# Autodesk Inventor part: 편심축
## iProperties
Company: 한국ATC센터
Created: 2014-01
Part Number: 편심축
Document SubType Name: Modeling
Designer: KYOUNG IL JANG
Density: 1 g/cm^3
Material: 기본값
Mass: 122.723 g
Surface Area: 190.471 cm^2
Volume: 122.723 cm^3
Vendor: CBT Solutions
Author: KYOUNG IL JANG
